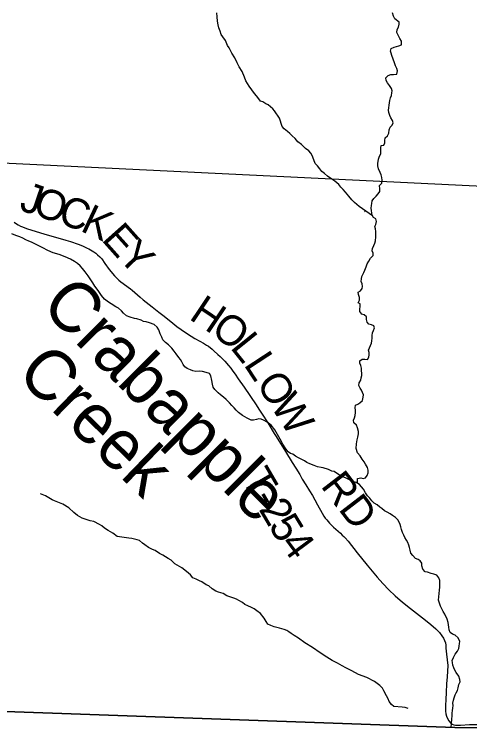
# Model space of a CAD drawing. Extents: x 0 to 34, y 0 to 22.
# Drawn here: x 3.221 to 4.079, y 16.635 to 17.981 of the extents above; entities that cross this region are included whole.
import ezdxf

# ---------------------------------------------------------------- set-up
doc = ezdxf.new("R2010")
doc.units = 0
for name, color, linetype in [('GM_X_Corporation', 7, 'Continuous'), ('GM_X_County', 7, 'Continuous'), ('GM_X_Minor_River', 7, 'Continuous'), ('GM_X_Minor_River_Text', 7, 'Continuous'), ('GM_X_Township_Road', 7, 'Continuous'), ('GM_X_Township_Road_Text', 7, 'Continuous')]:
    doc.layers.add(name, color=color, linetype=linetype)

msp = doc.modelspace()

# ---------------------------------------------------------------- linework, layer by layer
at = {"layer": 'GM_X_Corporation'}
for points in [[(9.4, 16.4853), (9.4, 20.4), (2.6, 20.4), (2.6, 16.6918), (3.1555, 16.6686), (3.1684, 16.6682), (4.0515, 16.6368), (4.1011, 16.6362), (4.1867, 16.6352), (4.5473, 16.6256), (4.6351, 16.6229), (5.4202, 16.5982), (6.0834, 16.5816), (6.2194, 16.578), (8.0963, 16.5226), (9.09, 16.4927)], [(6.2895, 20.4), (2.6, 20.4), (2.6, 16.6918), (3.1555, 16.6686), (3.1684, 16.6682), (4.0515, 16.6368), (4.1011, 16.6362), (4.1867, 16.6352), (4.5473, 16.6256), (4.6351, 16.6229), (5.4202, 16.5982), (6.0834, 16.5816), (6.2194, 16.578), (6.2729, 18.2077), (6.2744, 18.4654), (6.2786, 18.5898), (6.292, 18.5898), (6.2926, 19.1539), (6.2942, 19.6131), (6.2595, 19.6124)], [(4.2417, 18.6679), (4.2074, 17.6513), (3.1848, 17.7013), (3.2101, 18.7098)], [(2.6, 16.6918), (2.6, 13.6), (9.4, 13.6), (9.4, 16.4853), (9.09, 16.4927), (8.0963, 16.5226), (6.2194, 16.578), (6.0834, 16.5816), (5.4202, 16.5982), (4.6351, 16.6229), (4.5473, 16.6256), (4.1867, 16.6352), (4.1011, 16.6362), (4.0515, 16.6368), (3.1684, 16.6682), (3.1555, 16.6686)]]:
    msp.add_lwpolyline(points, close=True, dxfattribs=at)
msp.add_lwpolyline([(4.5473, 16.6256), (4.1867, 16.6352), (4.1011, 16.6362), (4.0515, 16.6368), (3.1684, 16.6682), (3.1555, 16.6686), (3.148, 15.8071)], dxfattribs=at)
at = {"layer": 'GM_X_County'}
msp.add_lwpolyline([(9.4, 16.4853), (9.09, 16.4927), (8.0963, 16.5226), (6.2194, 16.578), (6.0834, 16.5816), (5.4202, 16.5982), (4.6351, 16.6229), (4.5473, 16.6256), (4.1867, 16.6352), (4.1011, 16.6362), (4.0515, 16.6368), (3.1684, 16.6682), (3.1555, 16.6686), (2.6, 16.6918)], dxfattribs=at)
at = {"layer": 'GM_X_Minor_River'}
for points in [[(3.857, 17.6316), (3.8512, 17.6383), (3.8451, 17.6457), (3.8405, 17.651), (3.8366, 17.6554), (3.8328, 17.6603), (3.8252, 17.6666), (3.8194, 17.6703), (3.811, 17.6762), (3.8053, 17.6807), (3.8003, 17.6847), (3.7969, 17.6896), (3.7926, 17.6952), (3.788, 17.6997), (3.7857, 17.7064), (3.7822, 17.7147), (3.7795, 17.7191), (3.776, 17.7236), (3.7699, 17.7281), (3.7623, 17.7355), (3.755, 17.7403), (3.75, 17.747), (3.7443, 17.7522), (3.7401, 17.7563), (3.7355, 17.76), (3.7297, 17.7649), (3.7259, 17.7693), (3.7236, 17.7749), (3.7224, 17.7798), (3.7208, 17.7855), (3.7115, 17.7989), (3.7081, 17.803), (3.6993, 17.8104), (3.6951, 17.8122), (3.689, 17.8159), (3.6848, 17.8174), (3.6814, 17.8219), (3.6775, 17.8271), (3.6733, 17.8315), (3.6687, 17.8383), (3.6633, 17.8454), (3.6571, 17.8558), (3.6548, 17.8622), (3.6501, 17.873), (3.6447, 17.882), (3.6408, 17.8895), (3.6362, 17.8988), (3.6308, 17.9078), (3.6257, 17.9179), (3.6226, 17.9224), (3.6187, 17.9314), (3.6141, 17.9384), (3.611, 17.9429), (3.6091, 17.9493), (3.6063, 17.9556), (3.6048, 17.9609), (3.6035, 17.9677), (3.6031, 17.9763), (3.6026, 17.9838)], [(3.9025, 17.5613), (3.9024, 17.5714), (3.9015, 17.5767), (3.9004, 17.5808), (3.9022, 17.585), (3.9033, 17.5903), (3.9021, 17.5952), (3.8979, 17.5981), (3.8952, 17.6023), (3.8948, 17.6064), (3.8939, 17.6113), (3.8935, 17.6158), (3.8942, 17.6203), (3.8945, 17.6245), (3.8956, 17.6294), (3.8986, 17.634), (3.9027, 17.6385), (3.9068, 17.6423), (3.9098, 17.6469), (3.9097, 17.6518), (3.9093, 17.6582), (3.9138, 17.6628), (3.9141, 17.6684), (3.9133, 17.6733), (3.9121, 17.6782), (3.9105, 17.6831), (3.9074, 17.6898), (3.9062, 17.6951), (3.9062, 17.6996), (3.9076, 17.7079), (3.9094, 17.7135), (3.9116, 17.7181), (3.9119, 17.7226), (3.9119, 17.729), (3.9126, 17.7339), (3.9175, 17.7344), (3.9193, 17.7389), (3.9193, 17.743), (3.9196, 17.7479), (3.9245, 17.7521), (3.927, 17.7571), (3.9274, 17.7631), (3.9292, 17.768), (3.9333, 17.7718), (3.9351, 17.7767), (3.934, 17.7808), (3.9305, 17.7857), (3.9285, 17.7902), (3.927, 17.7958), (3.9262, 17.8003), (3.9269, 17.8048), (3.9276, 17.8097), (3.9279, 17.8139), (3.9286, 17.8188), (3.93, 17.8233), (3.9315, 17.8282), (3.9326, 17.8328), (3.9333, 17.8369), (3.9317, 17.8414), (3.9283, 17.847), (3.9244, 17.8518), (3.9217, 17.8559), (3.9213, 17.8612), (3.9258, 17.8654), (3.9307, 17.8677), (3.9356, 17.8678), (3.942, 17.8682), (3.9434, 17.8746), (3.9419, 17.8791), (3.9392, 17.8836), (3.9372, 17.8892), (3.9352, 17.8967), (3.9325, 17.9035), (3.9309, 17.9076), (3.9301, 17.9117), (3.9312, 17.9162), (3.9369, 17.9189), (3.941, 17.9205), (3.9455, 17.9217), (3.9504, 17.9236), (3.9504, 17.9304), (3.9473, 17.9352), (3.9457, 17.9393), (3.9418, 17.9468), (3.9425, 17.9521), (3.9447, 17.9566), (3.9462, 17.9623), (3.9461, 17.9664), (3.9381, 17.9723), (3.9354, 17.9772), (3.9338, 17.9836)], [(3.8962, 17.6009), (3.8708, 17.6185), (3.8666, 17.6223), (3.862, 17.626), (3.857, 17.6316)], [(3.881, 17.609), (3.8813, 17.6088)], [(3.2842, 17.536), (3.2743, 17.5408), (3.2633, 17.5467), (3.258, 17.5493), (3.2534, 17.5518), (3.2481, 17.5537), (3.2424, 17.5562), (3.237, 17.5592), (3.2309, 17.5618), (3.2237, 17.5639), (3.2161, 17.5672)], [(3.868, 17.0967), (3.868, 17.1059), (3.8737, 17.1071), (3.8782, 17.106), (3.8831, 17.1076), (3.8857, 17.1118), (3.8876, 17.1167), (3.8879, 17.1217), (3.8867, 17.1266), (3.8828, 17.1329), (3.8801, 17.1374), (3.8767, 17.1427), (3.8728, 17.1487), (3.8678, 17.1547), (3.8651, 17.1626), (3.8657, 17.1717), (3.8672, 17.1789), (3.8682, 17.1842), (3.8697, 17.1902), (3.8696, 17.1948), (3.8677, 17.2019), (3.8657, 17.2068), (3.8611, 17.2113), (3.8603, 17.2162), (3.8618, 17.2204), (3.8632, 17.2249), (3.8639, 17.2306), (3.8639, 17.2351), (3.8631, 17.2396), (3.8641, 17.2442), (3.8683, 17.2461), (3.8724, 17.2485), (3.8769, 17.253), (3.8784, 17.2595), (3.8791, 17.264), (3.8752, 17.2723), (3.8729, 17.2764), (3.8705, 17.2813), (3.8709, 17.2862), (3.8738, 17.2915), (3.8749, 17.2957), (3.8756, 17.3002), (3.8756, 17.3044), (3.8751, 17.3093), (3.8754, 17.3142), (3.8739, 17.3191), (3.8723, 17.3232), (3.8723, 17.3281), (3.8764, 17.3308), (3.8813, 17.3313), (3.8866, 17.3306), (3.8892, 17.3348), (3.8895, 17.3393), (3.8895, 17.3434), (3.8887, 17.348), (3.8905, 17.3525), (3.8942, 17.3609), (3.8949, 17.3658), (3.8952, 17.3703), (3.8952, 17.3756), (3.8963, 17.3805), (3.8981, 17.3851), (3.8996, 17.39), (3.8984, 17.3941), (3.8942, 17.396), (3.8893, 17.3967), (3.8862, 17.4008), (3.8846, 17.4057), (3.8849, 17.411), (3.8803, 17.4143), (3.8758, 17.4157), (3.8719, 17.421), (3.8719, 17.4255), (3.8726, 17.4304), (3.8729, 17.435), (3.8687, 17.4372), (3.8713, 17.4421), (3.8716, 17.4474), (3.8693, 17.4526), (3.8689, 17.4572), (3.8734, 17.4599), (3.8764, 17.464), (3.8774, 17.4682), (3.8766, 17.4727), (3.8747, 17.4772), (3.875, 17.4821), (3.8761, 17.4871), (3.8798, 17.4943), (3.8813, 17.4988), (3.8842, 17.5049), (3.886, 17.5106), (3.889, 17.5159), (3.8923, 17.5216), (3.8972, 17.5265), (3.8972, 17.531), (3.8956, 17.5352), (3.8959, 17.5393), (3.8985, 17.545), (3.9007, 17.5496), (3.9018, 17.5541), (3.9025, 17.5613)], [(3.8392, 17.1101), (3.832, 17.1138), (3.8239, 17.119), (3.8194, 17.1201), (3.8129, 17.123), (3.803, 17.1263), (3.7989, 17.127), (3.7924, 17.1284), (3.786, 17.1306), (3.7776, 17.1336), (3.7719, 17.1365), (3.7677, 17.1391), (3.7563, 17.145), (3.7509, 17.148), (3.7456, 17.1517), (3.7414, 17.1532), (3.7368, 17.1565), (3.7326, 17.1621), (3.7272, 17.1707), (3.7218, 17.1805), (3.7171, 17.1891), (3.7117, 17.1981), (3.7048, 17.2064), (3.6972, 17.212), (3.6903, 17.216), (3.6858, 17.2179), (3.6816, 17.2186), (3.6771, 17.2174), (3.6714, 17.2162), (3.6672, 17.2161), (3.6596, 17.2198), (3.6512, 17.225), (3.6436, 17.2306), (3.639, 17.235), (3.6352, 17.2392), (3.631, 17.244), (3.6267, 17.2485), (3.6199, 17.2548), (3.6153, 17.2593), (3.6095, 17.2638), (3.6049, 17.2675), (3.5988, 17.2738), (3.5957, 17.2783), (3.5945, 17.284), (3.5929, 17.2911), (3.591, 17.2994), (3.5886, 17.3039), (3.5822, 17.3061), (3.5757, 17.3079), (3.5689, 17.3082), (3.5632, 17.3078), (3.5575, 17.3092), (3.553, 17.3107), (3.5465, 17.3132), (3.5419, 17.3166), (3.5392, 17.3211), (3.5365, 17.3259), (3.5342, 17.3301), (3.5307, 17.3342), (3.5257, 17.3409), (3.5223, 17.3458), (3.5177, 17.3518), (3.5112, 17.3581), (3.5058, 17.3622), (3.5008, 17.3674), (3.4989, 17.3727), (3.4958, 17.379), (3.493, 17.3866), (3.4899, 17.3914), (3.4842, 17.3963), (3.4755, 17.3996), (3.469, 17.4014), (3.4645, 17.4021), (3.4599, 17.4046), (3.4515, 17.4072), (3.447, 17.4079), (3.4394, 17.4101), (3.4325, 17.4126), (3.4268, 17.4174), (3.4226, 17.4219), (3.4169, 17.4271), (3.4119, 17.4297), (3.4035, 17.4353), (3.3982, 17.4382), (3.3909, 17.4442), (3.3852, 17.4509), (3.3798, 17.4584), (3.3771, 17.4629), (3.3728, 17.4688), (3.369, 17.4748), (3.3597, 17.4883), (3.3544, 17.4958), (3.3494, 17.5017), (3.3451, 17.5066), (3.3398, 17.5111), (3.3341, 17.5151), (3.3264, 17.5196), (3.3169, 17.5236), (3.3055, 17.528), (3.2941, 17.5316), (3.2842, 17.536)], [(4.0443, 16.6368), (4.0461, 16.6595), (4.0464, 16.6637), (4.0471, 16.6686), (4.0474, 16.6732), (4.0478, 16.6785), (4.0477, 16.683), (4.0484, 16.6883), (4.0499, 16.6929), (4.0521, 16.6982), (4.0539, 16.7024), (4.0565, 16.7066), (4.0576, 16.7119), (4.0587, 16.718), (4.0613, 16.7229), (4.0605, 16.7275), (4.0585, 16.7335), (4.0535, 16.7406), (4.0512, 16.7452), (4.0492, 16.7493), (4.0477, 16.7542), (4.0468, 16.7591), (4.046, 16.7633), (4.049, 16.7686), (4.052, 16.7751), (4.0561, 16.7804), (4.0587, 16.7858), (4.0594, 16.7903), (4.0601, 16.7949), (4.0608, 16.7991), (4.0577, 16.8058), (4.0519, 16.8107), (4.0466, 16.8125), (4.0424, 16.8159), (4.0408, 16.8212), (4.0397, 16.8261), (4.0392, 16.8302), (4.0384, 16.8348), (4.0365, 16.8412), (4.0326, 16.8502), (4.0295, 16.8555), (4.0264, 16.8604), (4.0241, 16.8656), (4.0221, 16.8709), (4.0205, 16.8766), (4.0208, 16.883), (4.0215, 16.8895), (4.0222, 16.8955), (4.0229, 16.9012), (4.0232, 16.9084), (4.0228, 16.9141), (4.0208, 16.919), (4.0173, 16.9239), (4.0116, 16.9261), (4.0067, 16.9271), (3.9995, 16.9293), (3.9953, 16.9304), (3.9907, 16.9353), (3.9891, 16.9417), (3.9891, 16.9466), (3.986, 16.9511), (3.9818, 16.9533), (3.9772, 16.9555), (3.9723, 16.9608), (3.9684, 16.9657), (3.9668, 16.9709), (3.9656, 16.9762), (3.9648, 16.9804), (3.9625, 16.9856), (3.9602, 16.9901), (3.9567, 16.995), (3.9552, 16.9992), (3.9524, 17.0044), (3.9509, 17.0101), (3.9493, 17.015), (3.9481, 17.0195), (3.9465, 17.0237), (3.9435, 17.0282), (3.9396, 17.0323), (3.9339, 17.0364), (3.929, 17.0393), (3.9236, 17.0427), (3.9183, 17.0453), (3.9137, 17.0494), (3.9095, 17.0523), (3.9045, 17.0564), (3.8992, 17.0598), (3.8946, 17.0643), (3.8908, 17.0688), (3.8865, 17.0736), (3.8827, 17.0789), (3.8788, 17.086), (3.875, 17.0905), (3.8712, 17.0946), (3.8654, 17.0983), (3.8586, 17.1005), (3.8487, 17.1053), (3.8392, 17.1101)], [(3.963, 16.6729), (3.9573, 16.6744), (3.9517, 16.6751), (3.9361, 16.6764), (3.9315, 16.6805), (3.9273, 16.6858), (3.9254, 16.6907), (3.9223, 16.6963), (3.9172, 16.7057), (3.9149, 16.711), (3.9095, 16.7159), (3.9, 16.7237), (3.8855, 16.7311), (3.8696, 16.737), (3.857, 16.7436), (3.8456, 16.7496), (3.8387, 16.7533), (3.83, 16.7581), (3.8201, 16.7633), (3.8101, 16.7696), (3.7976, 16.7774), (3.7831, 16.7874), (3.7686, 16.7967), (3.7564, 16.8049), (3.7484, 16.8105), (3.7426, 16.8138), (3.7384, 16.8172), (3.7342, 16.8194), (3.7293, 16.8216), (3.7209, 16.8238), (3.7107, 16.8263), (3.7042, 16.8289), (3.6989, 16.8315), (3.6954, 16.8367), (3.692, 16.8431), (3.685, 16.8518), (3.6778, 16.8566), (3.6732, 16.8607), (3.6679, 16.8633), (3.661, 16.8662), (3.6553, 16.8688), (3.6507, 16.8725), (3.6439, 16.8762), (3.6397, 16.8785), (3.6348, 16.8803), (3.6268, 16.8829), (3.6211, 16.8847), (3.6146, 16.8891), (3.6058, 16.8921), (3.6005, 16.8939), (3.594, 16.8984), (3.5872, 16.9036), (3.5826, 16.9058), (3.5742, 16.9114), (3.5696, 16.9132), (3.5636, 16.9165), (3.5575, 16.9191), (3.5529, 16.9247), (3.5452, 16.9311), (3.5364, 16.9378), (3.528, 16.9426), (3.5231, 16.9452), (3.5166, 16.9523), (3.5109, 16.9552), (3.5006, 16.9619), (3.4945, 16.9645), (3.4861, 16.9704), (3.4815, 16.9723), (3.4735, 16.9763), (3.4667, 16.9812), (3.4625, 16.9842), (3.4567, 16.989), (3.4522, 16.9905), (3.4423, 16.993), (3.4366, 16.9937), (3.4279, 16.9951), (3.4233, 16.9954), (3.4146, 16.9968), (3.4062, 17.0028), (3.3975, 17.0079), (3.3906, 17.0124), (3.3856, 17.0169), (3.3811, 17.0195), (3.3708, 17.025), (3.3639, 17.0264), (3.3487, 17.0315), (3.34, 17.0364), (3.3331, 17.0423), (3.3235, 17.0509), (3.3121, 17.0576), (3.303, 17.0612), (3.2965, 17.0638), (3.2919, 17.0656), (3.2797, 17.0734), (3.2702, 17.0775)]]:
    msp.add_lwpolyline(points, dxfattribs=at)
at = {"layer": 'GM_X_Township_Road'}
for points in [[(3.2206, 17.5891), (3.2246, 17.5863), (3.2282, 17.584), (3.2323, 17.5818), (3.2359, 17.5801), (3.2404, 17.5785), (3.2453, 17.5767), (3.2761, 17.5672), (3.3176, 17.5555), (3.3264, 17.553), (3.3414, 17.548), (3.3495, 17.5445), (3.3545, 17.5422), (3.3582, 17.5404), (3.3614, 17.5388), (3.3641, 17.5373), (3.3677, 17.5352), (3.3708, 17.5331), (3.3742, 17.5306), (3.3775, 17.5279), (3.3817, 17.5241), (3.3854, 17.52), (3.3916, 17.5115), (3.3998, 17.4998), (3.4098, 17.4879), (3.4125, 17.4849), (3.4152, 17.4823), (3.4176, 17.4802), (3.4216, 17.4769), (3.4396, 17.4633), (3.4427, 17.461), (3.4578, 17.4476), (3.4637, 17.4429), (3.469, 17.4386), (3.4805, 17.4294), (3.493, 17.4196), (3.5034, 17.4119), (3.5194, 17.399), (3.5271, 17.3926), (3.5353, 17.3868), (3.5415, 17.3825), (3.5539, 17.3741), (3.5608, 17.3702), (3.5702, 17.3652), (3.5772, 17.3613), (3.5833, 17.3577), (3.5868, 17.3552), (3.5935, 17.3498), (3.5968, 17.3469), (3.6043, 17.3401), (3.609, 17.3358), (3.6134, 17.3317), (3.6176, 17.3275), (3.6248, 17.3192), (3.6291, 17.3141), (3.6328, 17.3085), (3.637, 17.3025), (3.6429, 17.2942), (3.6542, 17.2784), (3.6765, 17.2448), (3.6816, 17.237)], [(3.6816, 17.237), (3.6878, 17.2275), (3.6986, 17.2109), (3.7109, 17.1909), (3.7144, 17.1853), (3.7319, 17.1571), (3.7446, 17.1365), (3.7512, 17.1258), (3.7589, 17.1135), (3.7637, 17.1049), (3.7703, 17.0939), (3.7774, 17.0829), (3.7827, 17.0742), (3.7872, 17.0662), (3.7921, 17.0567), (3.8011, 17.0408), (3.8045, 17.0351), (3.8069, 17.0316), (3.8097, 17.028), (3.8123, 17.0249), (3.8149, 17.0219), (3.8181, 17.0186), (3.8225, 17.0146), (3.8354, 17.0029), (3.8391, 16.9995), (3.8422, 16.9966), (3.8443, 16.9944), (3.85, 16.9879), (3.8673, 16.9659), (3.8861, 16.9426), (3.9049, 16.92), (3.9153, 16.9084), (3.9269, 16.8961), (3.939, 16.8849), (3.9528, 16.8729), (3.9675, 16.8611), (3.9958, 16.8389), (4.0061, 16.8307), (4.0157, 16.8229), (4.0221, 16.8161), (4.0269, 16.8099), (4.0297, 16.8054), (4.0319, 16.8008), (4.0334, 16.7966), (4.0342, 16.7917), (4.0345, 16.7866), (4.0354, 16.7751), (4.0368, 16.7646), (4.0377, 16.7539), (4.0367, 16.7322), (4.0358, 16.7193), (4.0349, 16.703), (4.0343, 16.6895), (4.0339, 16.6784), (4.0337, 16.6679), (4.0344, 16.6626), (4.0354, 16.658), (4.0371, 16.654), (4.0402, 16.6491), (4.0436, 16.6452), (4.0462, 16.6433), (4.0491, 16.6419), (4.0526, 16.6411), (4.0622, 16.6414), (4.0791, 16.6422), (4.102, 16.6428)]]:
    msp.add_lwpolyline(points, dxfattribs=at)

# ---------------------------------------------------------------- texts
at = {"layer": 'GM_X_Minor_River_Text'}
for s, height, rotation, p in [('Crabapple', 0.09443, 315.0037, (3.268, 17.4292)), ('Creek', 0.09444, 315.8892, (3.2221, 17.3004))]:
    msp.add_text(s, height=height, rotation=rotation, dxfattribs=at).set_placement(p)
at = {"layer": 'GM_X_Township_Road_Text'}
for s, height, rotation, p in [('J', 0.0568, 341.2486, (3.228, 17.6128)), ('O', 0.0568, 341.2494, (3.2533, 17.6042)), ('C', 0.0568, 341.0078, (3.3005, 17.5882)), ('K', 0.0568, 334.7497, (3.3432, 17.5736)), ('E', 0.0568, 311.6965, (3.3836, 17.5559)), ('Y', 0.0568, 314.3299, (3.4138, 17.522)), ('H', 0.0568, 326.1003, (3.5483, 17.4077)), ('O', 0.0568, 323.0645, (3.5891, 17.3803)), ('L', 0.0568, 308.8137, (3.6264, 17.3528)), ('L', 0.0568, 303.2325, (3.6522, 17.3209)), ('O', 0.0568, 302.6817, (3.6754, 17.2855)), ('W', 0.0568, 302.6802, (3.7024, 17.2434)), ('T', 0.0568, 300.2244, (3.6473, 17.1055)), ('RD', 0.05682, 307.5686, (3.7969, 17.0919)), ('-', 0.0568, 300.2693, (3.6687, 17.0688)), ('2', 0.0568, 300.4827, (3.6806, 17.0484)), ('5', 0.0568, 301.2436, (3.6988, 17.0175)), ('4', 0.0568, 306.5943, (3.7202, 16.9828))]:
    msp.add_text(s, height=height, rotation=rotation, dxfattribs=at).set_placement(p)

doc.saveas('drawing.dxf')
